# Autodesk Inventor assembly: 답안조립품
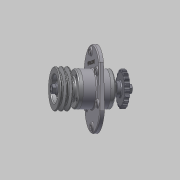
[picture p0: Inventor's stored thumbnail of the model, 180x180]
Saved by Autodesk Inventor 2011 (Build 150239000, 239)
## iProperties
Created: 2015-02
Part Number: 답안조립품
Document SubType Name: Assembly
Designer: user
Author: user
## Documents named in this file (12)
- C:\Users\user\Desktop\450208V1001\답안조립품.iam
- C:\Users\user\Desktop\450208V1001\9-M16-너트.ipt
- C:\Users\user\Desktop\450208V1001\10-M6.ipt
- C:\Users\user\Desktop\450208V1001\11-키 6x6.ipt
- C:\Users\user\Desktop\450208V1001\1_본체.ipt
- C:\Users\user\Desktop\450208V1001\2-커버.ipt
- C:\Users\user\Desktop\450208V1001\3-축.ipt
- C:\Users\user\Desktop\450208V1001\4-V벨트풀리.ipt
- C:\Users\user\Desktop\450208V1001\5-체인 스프로킷.ipt
- C:\Users\user\Desktop\450208V1001\6-베어링 6206.ipt
- C:\Users\user\Desktop\450208V1001\7-부시.ipt
- C:\Users\user\Desktop\450208V1001\8-오일실 30x42.ipt
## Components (23 placed, 11 different names)
1. 9-M16 너트:1
2. 1_본체:1
3. 2-커버:1
4. 3-축:1
5. 4-V벨트풀리:1
6. 5-체인 스프로킷:1
7. 6-베어링 6206:1
8. 7-부시:1
9. 8-8-오일실 30x42:1
10. 6-베어링 6206:2
11. 2-커버:2
12. 8-8-오일실 30x42:2
13. 11-키 6x6:2
14. 11-키 6x6:3
15. 9-M16 너트:2
16. 10-M6:1
17. 10-M6:3
18. 10-M6:4
19. 10-M6:5
20. 10-M6:2
21. 10-M6:6
22. 10-M6:7
23. 10-M6:8
